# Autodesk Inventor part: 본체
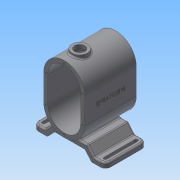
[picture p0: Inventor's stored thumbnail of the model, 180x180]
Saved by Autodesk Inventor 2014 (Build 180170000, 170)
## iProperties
Created: 2016-12
Part Number: 본체
Material: 알루미늄 6061
Document SubType Name: Modeling
Designer: mduedu
Density: 2.71 g/cm^3
Appearance: 기본값
Mass: 1017.21 g
Surface Area: 965.782 cm^2
Volume: 375.354 cm^3
Author: mduedu
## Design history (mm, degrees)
sketch "스케치1"
  geometry: L1 (40, -25)-(40, 25); L2 (-40, 25)-(-40, -25); L3 (-40, -25)-(40, 25); L4 (40, -25)-(-40, 25); L5 (0, 25)-(0, -25); A1 r 40 centre (0, 25) between (40, 25) and (-40, 25); A2 r 40 centre (0, -25) between (-40, -25) and (40, -25); 1 further point
  constraints: 10 end point, 4 point on circle, 3 tangent, 2 centre point, 2 midpoint, 2 parallel, 1 vertical
  dimensions: "d0" = 130 dimension on A2 A1; "d2" = 80 distance between parallel lines of L1 L2
extrude "돌출1" new body sketch "스케치1" stored distance "d3" = 100; taper "d4" = 0 deg
feature "쉘1" dims "d5" = 8
sketch "스케치15"
  geometry: L1 (-35, -64.5)-(35, -64.5); L2 (-35, -64.5)-(-47.586, -79.5); L3 (-47.586, -79.5)-(-70, -79.5); L4 (0, -64.5)-(0, 0); L5 (35, -64.5)-(47.586, -79.5); L6 (47.586, -79.5)-(70, -79.5); L7 (70, -89.5)-(42.923, -89.5); L8 (42.923, -89.5)-(30.337, -74.5); L9 (30.337, -74.5)-(-30.337, -74.5); L10 (-30.337, -74.5)-(-42.923, -89.5); L11 (-42.923, -89.5)-(-70, -89.5); L12 (-70, -79.5)-(-70, -89.5); L13 (70, -79.5)-(70, -89.5); A1 r 40 centre (0, -25) between (-40, -25) and (40, -25) reference; 1 further point
  constraints: 26 end point, 2 parallel, 2 perpendicular, 2 symmetric about line, 1 coincident, 1 horizontal, 1 midpoint, 1 vertical, 4 other
  dimensions: "d83" = 10 distance between parallel lines of L9 L1; "d85" = 140 distance between parallel lines of L13 L12; "d86" = 70 distance of L1.start L1.end; "d87" = 25 distance between parallel lines of L11 L1; "d88" = 130 deg angle of L1 L2; "d106" = 0.5 distance edge to line of A1 L1
extrude "돌출6" new body sketch "스케치15" stored distance "d89" = 80; taper "d90" = 0 deg
fillet "모깎기13" dims "d101" = 3
fillet "모깎기15" dims "d103" = 3
fillet "모깎기16" dims "d104" = 10
fillet "모깎기17" dims "d105" = 3
feature "결합2"
  node "솔리드2"
fillet "모깎기18" dims "d107" = 3
sketch "스케치16"
  geometry: L1 (8.015, 67)-(8.015, 7); L2 (14.015, 67)-(14.015, 7); A1 r 10 centre (11.015, 67) between (21.015, 67) and (11.015, 77) reference; A2 r 10 centre (11.015, 7) between (11.015, -3) and (21.015, 7) reference; A3 r 3 centre (11.015, 67) between (8.015, 67) and (14.015, 67); A4 r 3 centre (11.015, 7) between (8.015, 7) and (14.015, 7); 1 further point
  constraints: 4 end point, 4 point on circle, 4 tangent, 2 centre point, 2 coincident
  dimensions: "d108" = 6 diameter of A3; "d109" = 6 diameter of A4
extrude "돌출7" cut sketch "스케치16" stored distance "d110" = 80; taper "d111" = 0 deg
node "작업 평면1"
sketch "스케치9"
  geometry: 1 further point
sketch "스케치7"
  geometry: L1 (40, 50)-(-40, 50) reference; C1 r 15 at (0, 20); 1 further point
  constraints: 1 centre point, 1 vertical alignment
  dimensions: "d40" = 30 diameter of C1; "d41" = 30 distance from line of C1.centre L1
extrude "돌출4" join sketch "스케치7" stored distance "d42" = 80; taper "d43" = 0 deg
hole "구멍2" diameter "d46" = 20; stored, may be unused: countersink angle "d50" = 90 deg, drill point angle "d52" = 118 deg; dims "d44" = 10, "d45" = 10, "d47" = 6, "d48" = 4, "d49" = 2, "d51" = 8
fillet "모깎기4" dims "d53" = 3
node "작업 평면2"
sketch "스케치8"
  geometry: C1 r 15 at (0, 0) reference; C2 r 15 at (0, 0); 1 further point
  constraints: 1 centre point, 1 coincident
  dimensions: "d55" = 30 diameter of C2
extrude "돌출5" cut sketch "스케치8" stored distance "d56" = 80; taper "d57" = 0 deg
chamfer "모따기1" distance "d58" = 1; stored, may be unused: second distance "d59" = 2, angle "d60" = 45 deg
sketch "스케치10"
  geometry: 2 further points
  constraints: 1 coincident, 1 other
feature "엠보싱1" sketch "스케치10" dims "d0" = 130, "d2" = 80, "d61" = 0.5, "d62" = 0
sketch "스케치11"
  geometry: 1 further point
  constraints: 1 other
hole "구멍3" sketch "스케치11" at (0, 60) diameter "d63" = 3.242; stored, may be unused: countersink angle "d67" = 90 deg, drill point angle "d69" = 120 deg; dims "d64" = 8.6, "d65" = 4, "d66" = 2, "d68" = 10.6
sketch "스케치12"
  geometry: 1 further point
  constraints: 1 other
hole "구멍5" sketch "스케치12" at (0, 60) diameter "d70" = 3.242; stored, may be unused: countersink angle "d74" = 90 deg, drill point angle "d76" = 120 deg; dims "d71" = 8.6, "d72" = 4, "d73" = 2, "d75" = 10.6
node "솔리드1"
mirror "대칭2"
pattern_linear "직사각형 패턴1"
pattern_linear "직사각형 패턴2"
sketch "스케치13"
  geometry: L1 (-40, 25)-(-40, -25) reference; L2 (40, -25)-(40, 25) reference; L3 (35, 25)-(35, -25); L4 (-35, -25)-(-35, 25); A1 r 40 centre (0, 25) between (40, 25) and (-40, 25) reference; A2 r 40 centre (0, -25) between (-40, -25) and (40, -25) reference; A3 r 35 centre (0, 25) between (35, 25) and (-35, 25); A4 r 35 centre (0, -25) between (-35, -25) and (35, -25); 2 further points
  constraints: 5 point on circle, 4 end point, 2 centre point, 3 other
  dimensions: "d77" = 5 distance between parallel lines of L3 L2
sketch "스케치14"
  geometry: L1 (-40, 25)-(-40, -25) reference; L2 (40, -25)-(40, 25) reference; L3 (35, 25)-(35, -25); L4 (-35, -25)-(-35, 25); A1 r 40 centre (0, 25) between (40, 25) and (-40, 25) reference; A2 r 40 centre (0, -25) between (-40, -25) and (40, -25) reference; A3 r 35 centre (0, 25) between (35, 25) and (-35, 25); A4 r 35 centre (0, -25) between (-35, -25) and (35, -25); 2 further points
  constraints: 5 point on circle, 4 end point, 2 centre point, 3 other
  dimensions: "d80" = 5 distance between parallel lines of L2 L3
other parameters: "d54" = -8
